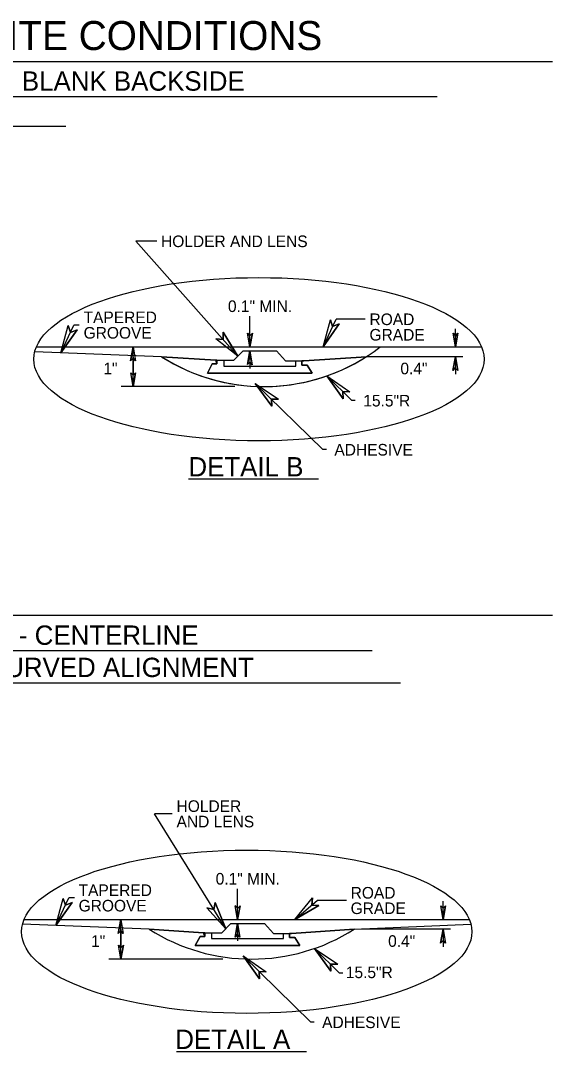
# Model space of a CAD drawing. Extents: x 12.2 to 19.6, y 5.9 to 16.3.
# Drawn here: x 16.87 to 19.62, y 10.95 to 16.28 of the extents above; entities that cross this region are included whole.
import ezdxf

# ---------------------------------------------------------------- set-up
doc = ezdxf.new("R2010")
doc.units = 0
for name, color, linetype in [('BORD-LINE', 7, 'Continuous'), ('DETL-DIMS', 7, 'Continuous'), ('DETL-LINE', 7, 'Continuous'), ('DETL-NOTE', 7, 'Continuous'), ('DETL-TITL', 7, 'Continuous')]:
    doc.layers.add(name, color=color, linetype=linetype)

msp = doc.modelspace()

# ---------------------------------------------------------------- linework, layer by layer
at = {"layer": 'BORD-LINE'}
msp.add_line((12.2466, 13.2092), (19.6208, 13.2092), dxfattribs=at)
at = {"layer": 'DETL-DIMS'}
for p, q in [((17.5757, 15.1427), (17.4666, 15.1427)), ((17.9954, 14.5487), (17.4666, 15.1427)), ((18.0572, 14.5959), (18.0572, 14.7551)), ((18.436, 14.5959), (18.5025, 14.7391)), ((18.436, 14.5959), (18.4734, 14.7362)), ((18.4849, 14.7011), (18.4734, 14.7362)), ((18.6533, 14.7391), (18.5025, 14.7391)), ((17.0804, 14.5661), (17.147, 14.7093)), ((17.0804, 14.5661), (17.1178, 14.7064)), ((17.0804, 14.5661), (17.1635, 14.6851)), ((17.1293, 14.6713), (17.1178, 14.7064)), ((17.1635, 14.6851), (17.1293, 14.6713)), ((17.1753, 14.7093), (17.147, 14.7093)), ((17.9191, 14.6722), (17.9182, 14.6353)), ((17.9954, 14.5487), (17.9191, 14.6722)), ((18.0572, 14.5959), (18.0451, 14.6675)), ((18.0576, 14.6539), (18.0451, 14.6675)), ((18.0572, 14.5959), (18.0703, 14.6673)), ((18.0703, 14.6673), (18.0576, 14.6539)), ((18.436, 14.5959), (18.5191, 14.715)), ((18.5191, 14.715), (18.4849, 14.7011)), ((19.1195, 14.5959), (19.1074, 14.6675)), ((19.1199, 14.6539), (19.1074, 14.6675)), ((19.1195, 14.5959), (19.1195, 14.6906)), ((19.1195, 14.5959), (19.1326, 14.6673)), ((19.1326, 14.6673), (19.1199, 14.6539)), ((17.9954, 14.5487), (17.8815, 14.6387)), ((17.9182, 14.6353), (17.8815, 14.6387)), ((17.4533, 14.5959), (17.4402, 14.5245)), ((17.4533, 14.3913), (17.4533, 14.5959)), ((17.4533, 14.5959), (17.4654, 14.5243)), ((18.0572, 14.5759), (18.0441, 14.5045)), ((18.0572, 14.5759), (18.0693, 14.5043)), ((18.0572, 14.5759), (18.0572, 14.4853)), ((17.4402, 14.5245), (17.4529, 14.5379)), ((17.4529, 14.5379), (17.4654, 14.5243)), ((17.4533, 14.5455), (17.4533, 14.4549)), ((18.0441, 14.5045), (18.0568, 14.5179)), ((18.0568, 14.5179), (18.0693, 14.5043)), ((19.1577, 14.5455), (18.6593, 14.5455)), ((19.1195, 14.5455), (19.1064, 14.4741)), ((19.1195, 14.5455), (19.1316, 14.4739)), ((19.1195, 14.5455), (19.1195, 14.4549)), ((17.4533, 14.3913), (17.4412, 14.4629)), ((17.4537, 14.4493), (17.4412, 14.4629)), ((17.4533, 14.3913), (17.4664, 14.4627)), ((17.4664, 14.4627), (17.4537, 14.4493)), ((19.1064, 14.4741), (19.1191, 14.4875)), ((19.1191, 14.4875), (19.1316, 14.4739)), ((18.0851, 14.4078), (18.4348, 14.0656)), ((18.0851, 14.4078), (18.1697, 14.2898)), ((18.0851, 14.4078), (18.2049, 14.3258)), ((18.4546, 14.4463), (18.5392, 14.3283)), ((18.4546, 14.4463), (18.5744, 14.3643)), ((18.4546, 14.4463), (18.5843, 14.3194)), ((17.98, 14.3913), (17.3919, 14.3913)), ((18.5392, 14.3283), (18.5375, 14.3651)), ((18.5375, 14.3651), (18.5744, 14.3643)), ((18.1697, 14.2898), (18.168, 14.3267)), ((18.168, 14.3267), (18.2049, 14.3258)), ((18.6018, 14.3194), (18.5843, 14.3194)), ((18.4524, 14.0656), (18.4348, 14.0656)), ((17.6559, 12.1812), (17.5638, 12.1812)), ((17.9319, 11.5871), (17.5638, 12.1812)), ((17.9937, 11.6343), (17.9937, 11.7935)), ((17.0547, 11.603), (17.1212, 11.7462)), ((17.0547, 11.603), (17.0921, 11.7433)), ((17.1036, 11.7082), (17.0921, 11.7433)), ((17.1496, 11.7462), (17.1212, 11.7462)), ((18.2887, 11.6343), (18.3815, 11.746)), ((18.2887, 11.6343), (18.4051, 11.7328)), ((18.3773, 11.7093), (18.3815, 11.746)), ((18.5559, 11.7328), (18.4051, 11.7328)), ((17.0547, 11.603), (17.1378, 11.7221)), ((17.1378, 11.7221), (17.1036, 11.7082)), ((17.9319, 11.5871), (17.8352, 11.6954)), ((17.8708, 11.6857), (17.8352, 11.6954)), ((17.878, 11.7219), (17.8708, 11.6857)), ((17.9319, 11.5871), (17.878, 11.7219)), ((17.9937, 11.6343), (17.9816, 11.7059)), ((17.9941, 11.6923), (17.9816, 11.7059)), ((17.9937, 11.6343), (18.0068, 11.7057)), ((18.0068, 11.7057), (17.9941, 11.6923)), ((18.2887, 11.6343), (18.4141, 11.7075)), ((18.4141, 11.7075), (18.3773, 11.7093)), ((19.056, 11.6343), (19.0439, 11.7059)), ((19.0564, 11.6923), (19.0439, 11.7059)), ((19.056, 11.6343), (19.056, 11.729)), ((19.056, 11.6343), (19.0691, 11.7057)), ((19.0691, 11.7057), (19.0564, 11.6923)), ((17.3899, 11.6343), (17.3768, 11.5629)), ((17.3899, 11.4297), (17.3899, 11.6343)), ((17.3899, 11.6343), (17.402, 11.5627)), ((17.3768, 11.5629), (17.3895, 11.5763)), ((17.3895, 11.5763), (17.402, 11.5627)), ((17.3899, 11.5839), (17.3899, 11.4933)), ((17.9937, 11.6143), (17.9806, 11.5429)), ((17.9937, 11.6143), (18.0058, 11.5427)), ((17.9937, 11.6143), (17.9937, 11.5237)), ((19.0942, 11.5839), (18.6349, 11.5839)), ((19.056, 11.5839), (19.0429, 11.5125)), ((19.056, 11.5839), (19.0681, 11.5123)), ((19.056, 11.5839), (19.056, 11.4933)), ((17.9806, 11.5429), (17.9933, 11.5563)), ((17.9933, 11.5563), (18.0058, 11.5427)), ((19.0429, 11.5125), (19.0556, 11.5259)), ((19.0556, 11.5259), (19.0681, 11.5123)), ((17.3899, 11.4297), (17.3778, 11.5013)), ((17.3903, 11.4877), (17.3778, 11.5013)), ((17.3899, 11.4297), (17.403, 11.5011)), ((17.403, 11.5011), (17.3903, 11.4877)), ((18.3911, 11.4847), (18.4757, 11.3667)), ((18.3911, 11.4847), (18.5109, 11.4027)), ((18.3911, 11.4847), (18.5208, 11.3578)), ((17.9166, 11.4297), (17.3284, 11.4297)), ((18.0216, 11.4462), (18.3713, 11.104)), ((18.0216, 11.4462), (18.1062, 11.3283)), ((18.0216, 11.4462), (18.1414, 11.3642)), ((18.1062, 11.3283), (18.1046, 11.3651)), ((18.1046, 11.3651), (18.1414, 11.3642)), ((18.4757, 11.3667), (18.474, 11.4035)), ((18.474, 11.4035), (18.5109, 11.4027)), ((18.5383, 11.3578), (18.5208, 11.3578)), ((18.3889, 11.104), (18.3713, 11.104))]:
    msp.add_line(p, q, dxfattribs=at)
for points in [[(18.5191, 14.715), (18.436, 14.5959), (18.4734, 14.7362), (18.4849, 14.7011)], [(17.1635, 14.6851), (17.0804, 14.5661), (17.1178, 14.7064), (17.1293, 14.6713)], [(17.9191, 14.6722), (17.9954, 14.5487), (17.8815, 14.6387), (17.9182, 14.6353)], [(18.0703, 14.6673), (18.0572, 14.5959), (18.0451, 14.6675), (18.0576, 14.6539)], [(19.1326, 14.6673), (19.1195, 14.5959), (19.1074, 14.6675), (19.1199, 14.6539)], [(17.4402, 14.5245), (17.4533, 14.5959), (17.4654, 14.5243), (17.4529, 14.5379)], [(18.0441, 14.5045), (18.0572, 14.5759), (18.0693, 14.5043), (18.0568, 14.5179)], [(19.1064, 14.4741), (19.1195, 14.5455), (19.1316, 14.4739), (19.1191, 14.4875)], [(17.4664, 14.4627), (17.4533, 14.3913), (17.4412, 14.4629), (17.4537, 14.4493)], [(18.1697, 14.2898), (18.0851, 14.4078), (18.2049, 14.3258), (18.168, 14.3267)], [(18.5392, 14.3283), (18.4546, 14.4463), (18.5744, 14.3643), (18.5375, 14.3651)], [(17.1378, 11.7221), (17.0547, 11.603), (17.0921, 11.7433), (17.1036, 11.7082)], [(18.4141, 11.7075), (18.2887, 11.6343), (18.3815, 11.746), (18.3773, 11.7093)], [(17.878, 11.7219), (17.9319, 11.5871), (17.8352, 11.6954), (17.8708, 11.6857)], [(18.0068, 11.7057), (17.9937, 11.6343), (17.9816, 11.7059), (17.9941, 11.6923)], [(19.0691, 11.7057), (19.056, 11.6343), (19.0439, 11.7059), (19.0564, 11.6923)], [(17.3768, 11.5629), (17.3899, 11.6343), (17.402, 11.5627), (17.3895, 11.5763)], [(17.9806, 11.5429), (17.9937, 11.6143), (18.0058, 11.5427), (17.9933, 11.5563)], [(19.0429, 11.5125), (19.056, 11.5839), (19.0681, 11.5123), (19.0556, 11.5259)], [(17.403, 11.5011), (17.3899, 11.4297), (17.3778, 11.5013), (17.3903, 11.4877)], [(18.4757, 11.3667), (18.3911, 11.4847), (18.5109, 11.4027), (18.474, 11.4035)], [(18.1062, 11.3283), (18.0216, 11.4462), (18.1414, 11.3642), (18.1046, 11.3651)]]:
    msp.add_lwpolyline(points, close=True, dxfattribs=at)
at = {"layer": 'DETL-LINE'}
for p, q in [((12.2466, 16.0733), (19.6208, 16.0733)), ((17.6003, 14.5455), (16.9449, 14.5714)), ((16.953, 14.5959), (19.255, 14.5959)), ((17.9749, 14.5274), (18.0217, 14.5759)), ((18.0217, 14.5759), (18.1954, 14.5759)), ((18.1954, 14.5759), (18.2419, 14.5242)), ((17.6003, 14.5455), (17.8816, 14.5274)), ((17.8628, 14.5082), (17.8384, 14.461)), ((17.8868, 14.5082), (17.8628, 14.5082)), ((17.8816, 14.5274), (17.9749, 14.5274)), ((17.8868, 14.5274), (17.8868, 14.5082)), ((17.9217, 14.5274), (17.9217, 14.497)), ((18.2419, 14.5242), (18.3363, 14.5242)), ((18.2951, 14.497), (18.2951, 14.5242)), ((18.3251, 14.5022), (18.3251, 14.5242)), ((18.3527, 14.5022), (18.3251, 14.5022)), ((18.3363, 14.5242), (18.6593, 14.5455)), ((18.3788, 14.461), (18.3527, 14.5022)), ((17.8384, 14.461), (18.3788, 14.461)), ((17.9217, 14.497), (18.2951, 14.497)), ((16.8896, 11.6343), (19.1915, 11.6343)), ((17.5368, 11.5839), (16.8814, 11.6098)), ((17.5368, 11.5839), (17.8181, 11.5658)), ((17.9114, 11.5658), (17.9582, 11.6143)), ((17.9582, 11.6143), (18.132, 11.6143)), ((18.132, 11.6143), (18.1784, 11.5626)), ((18.2729, 11.5626), (18.5959, 11.5839)), ((18.5959, 11.5839), (19.1997, 11.6098)), ((17.7993, 11.5466), (17.7749, 11.4994)), ((17.8234, 11.5466), (17.7993, 11.5466)), ((17.8181, 11.5658), (17.9114, 11.5658)), ((17.8234, 11.5658), (17.8234, 11.5466)), ((17.8582, 11.5658), (17.8582, 11.5354)), ((17.8582, 11.5354), (18.2316, 11.5354)), ((18.1784, 11.5626), (18.2729, 11.5626)), ((18.2316, 11.5354), (18.2316, 11.5626)), ((18.2616, 11.5406), (18.2616, 11.5626)), ((18.2893, 11.5406), (18.2616, 11.5406)), ((18.3153, 11.4994), (18.2893, 11.5406)), ((17.7749, 11.4994), (18.3153, 11.4994))]:
    msp.add_line(p, q, dxfattribs=at)
for centre, end in [((18.1298, 15.3772), 307.5845), ((18.0663, 12.4156), 302.4858)]:
    msp.add_arc(centre, 0.9859, 237.5142, end, dxfattribs=at)
for centre in [(18.104, 14.5328), (18.0405, 11.5712)]:
    msp.add_ellipse(centre, major_axis=(1.164, 0), ratio=0.362676, dxfattribs=at)
at = {"layer": 'DETL-NOTE'}
for p, q in [((17.8816, 14.5274), (17.8868, 14.5082)), ((17.8868, 14.5274), (17.8816, 14.5274)), ((17.8868, 14.5082), (17.8868, 14.5274)), ((17.8181, 11.5658), (17.8234, 11.5466)), ((17.8234, 11.5658), (17.8181, 11.5658)), ((17.8234, 11.5466), (17.8234, 11.5658))]:
    msp.add_line(p, q, dxfattribs=at)
for points in [[(18.6593, 14.5455), (18.3363, 14.5242), (18.3251, 14.5242), (18.3251, 14.5022), (18.3527, 14.5022), (18.3788, 14.461), (17.8384, 14.461), (17.8628, 14.5082), (17.8868, 14.5082), (17.8816, 14.5274), (17.6003, 14.5455)], [(18.5959, 11.5839), (18.2729, 11.5626), (18.2616, 11.5626), (18.2616, 11.5406), (18.2893, 11.5406), (18.3153, 11.4994), (17.7749, 11.4994), (17.7993, 11.5466), (17.8234, 11.5466), (17.8181, 11.5658), (17.5368, 11.5839)]]:
    msp.add_lwpolyline(points, dxfattribs=at)
for centre in [(18.1298, 15.3772), (18.0663, 12.4156)]:
    msp.add_arc(centre, 0.9859, 237.5142, 302.4858, dxfattribs=at)
at = {"layer": 'DETL-TITL'}
for p, q in [((12.8539, 15.8915), (19.0254, 15.8915)), ((14.7728, 15.7379), (17.105, 15.7379)), ((17.7405, 13.9139), (18.4124, 13.9139)), ((13.1831, 13.0257), (18.6888, 13.0257)), ((13.0328, 12.859), (18.836, 12.859)), ((17.677, 10.9524), (18.3489, 10.9524))]:
    msp.add_line(p, q, dxfattribs=at)

# ---------------------------------------------------------------- texts
at = {"layer": 'DETL-NOTE'}
for s, p in [('HOLDER AND LENS', (17.5977, 15.1125)), ('0.1" MIN.', (17.9436, 14.7768)), ('TAPERED', (17.1974, 14.7192)), ('ROAD', (18.6754, 14.7091)), ('GROOVE', (17.1974, 14.6392)), ('GRADE', (18.6754, 14.6291)), ('1"', (17.2997, 14.4547)), ('0.4"', (18.8352, 14.4547)), ('15.5"R', (18.6434, 14.2882)), ('ADHESIVE', (18.4939, 14.0344)), ('HOLDER', (17.6779, 12.1911)), ('AND LENS', (17.6779, 12.1111)), ('0.1" MIN.', (17.8802, 11.8152)), ('TAPERED', (17.1716, 11.7561)), ('ROAD', (18.5779, 11.7427)), ('GROOVE', (17.1716, 11.6761)), ('GRADE', (18.5779, 11.6627)), ('1"', (17.2362, 11.4931)), ('0.4"', (18.7717, 11.4931)), ('15.5"R', (18.5531, 11.3313)), ('ADHESIVE', (18.4304, 11.0728))]:
    msp.add_text(s, height=0.06, dxfattribs=at).set_placement(p)
at = {"layer": 'DETL-TITL'}
for s, height, p in [('RECESSED SRPM FOR RESTRICTIVE SITE CONDITIONS', 0.15, (13.0148, 16.1318)), ('RECESSED SRPM - SINGLE HOLDER & LENS - ONE WAY WITH BLANK BACKSIDE', 0.1, (12.8363, 15.9216)), ('DETAIL B', 0.1, (17.7394, 13.9264)), ('RECESSED SRPM - SINGLE HOLDER & LENS - TWO WAY - CENTERLINE', 0.1, (13.1775, 13.0553)), ('RESTRICTIVE SITE CONDITIONS - SHORT GROOVE FOR CURVED ALIGNMENT', 0.1, (13.0327, 12.8886)), ('DETAIL A', 0.1, (17.6713, 10.9649))]:
    msp.add_text(s, height=height, dxfattribs=at).set_placement(p)

doc.saveas('drawing.dxf')
